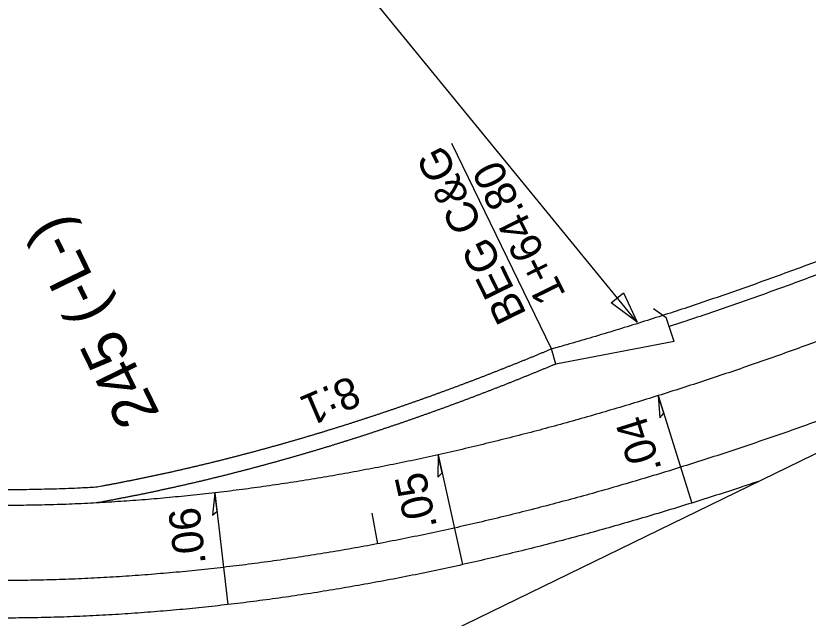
# Model space of a CAD drawing. Extents: x 2389694 to 2405615, y 546931 to 573532.
# Drawn here: x 2402110.3 to 2402237.1, y 570891.7 to 570988.1 of the extents above; entities that cross this region are included whole.
import ezdxf

# ---------------------------------------------------------------- set-up
doc = ezdxf.new("R2010")
doc.units = 0
for name, color, linetype in [('Old_Level_5', 7, 'Continuous'), ('Prop Cable Guiderail Single Face', 7, 'Continuous'), ('Prop Conc 2ft 6in Curb and Gutter', 7, 'Continuous'), ('Prop Conc Expressway Gutter', 7, 'Continuous'), ('Prop Dimension', 7, 'Continuous'), ('Prop Dimension Text', 7, 'Continuous'), ('Prop EOT', 7, 'Continuous'), ('Prop Horizontal Alignment', 7, 'Continuous'), ('Prop Horizontal Alignment Curve and Spiral Data', 7, 'Continuous'), ('Prop Horizontal Alignment Tick Small', 7, 'Continuous'), ('Prop Lane Lines', 7, 'Continuous'), ('Prop Super Arrow 1 Lane CELL', 7, 'Continuous'), ('Prop Superelevation Label', 7, 'Continuous')]:
    doc.layers.add(name, color=color, linetype=linetype)

msp = doc.modelspace()

# ---------------------------------------------------------------- linework, layer by layer
at = {"layer": 'Old_Level_5'}
msp.add_line((2402209.7, 570939.08), (2402131.29, 571034.89), dxfattribs=at)
msp.add_lwpolyline([(2402207.5, 570943.74), (2402209.7, 570939.08), (2402205.56, 570942.16)], close=True, dxfattribs=at)
at = {"layer": 'Prop Cable Guiderail Single Face'}
msp.add_spline([(2402278.77, 570901.45), (2402277.96, 570901.06), (2402277.14, 570900.67), (2402276.32, 570900.29), (2402275.51, 570899.9), (2402274.7, 570899.51), (2402273.88, 570899.13), (2402273.07, 570898.74), (2402272.26, 570898.36), (2402271.44, 570897.97), (2402270.63, 570897.58), (2402269.82, 570897.2), (2402269.01, 570896.81), (2402268.18, 570896.42), (2402267.37, 570896.04), (2402266.56, 570895.65), (2402265.74, 570895.26), (2402264.93, 570894.88), (2402264.12, 570894.49), (2402263.31, 570894.11), (2402262.49, 570893.72), (2402261.68, 570893.33), (2402260.87, 570892.95), (2402260.05, 570892.56), (2402259.24, 570892.18), (2402258.42, 570891.79), (2402257.6, 570891.4), (2402256.79, 570891.01), (2402255.98, 570890.63), (2402255.17, 570890.24), (2402254.35, 570889.86), (2402253.54, 570889.47), (2402252.73, 570889.08), (2402251.91, 570888.7), (2402251.1, 570888.31), (2402250.29, 570887.93), (2402249.47, 570887.53), (2402248.65, 570887.15), (2402247.84, 570886.76), (2402247.03, 570886.38), (2402246.21, 570885.99), (2402245.4, 570885.6), (2402244.59, 570885.22), (2402243.77, 570884.83), (2402242.96, 570884.45), (2402242.15, 570884.06), (2402241.33, 570883.67), (2402240.51, 570883.28), (2402239.7, 570882.9), (2402238.89, 570882.51), (2402238.07, 570882.13), (2402237.26, 570881.74), (2402236.45, 570881.35), (2402235.63, 570880.97), (2402234.82, 570880.58), (2402234.01, 570880.2), (2402233.19, 570879.81), (2402232.38, 570879.42), (2402231.56, 570879.03), (2402230.75, 570878.65), (2402229.93, 570878.26), (2402229.12, 570877.88), (2402228.31, 570877.49), (2402227.49, 570877.1), (2402226.68, 570876.72), (2402225.87, 570876.33), (2402225.06, 570875.95), (2402224.24, 570875.56), (2402223.43, 570875.17), (2402222.61, 570874.78), (2402221.79, 570874.4), (2402220.98, 570874.01), (2402220.17, 570873.62), (2402218.54, 570872.85)], degree=3, dxfattribs=at)
at = {"layer": 'Prop Conc 2ft 6in Curb and Gutter'}
msp.add_line((2402212.33, 570941.22), (2402214.37, 570939.78), dxfattribs=at)
for points in [[(2402196.02, 570934.77), (2402195.54, 570934.57), (2402195.07, 570934.37), (2402194.59, 570934.18), (2402194.11, 570933.98), (2402193.64, 570933.78), (2402193.16, 570933.58), (2402192.68, 570933.39), (2402192.2, 570933.19), (2402191.73, 570933), (2402191.25, 570932.81), (2402190.77, 570932.61), (2402190.29, 570932.42), (2402189.81, 570932.23), (2402189.33, 570932.04), (2402188.85, 570931.85), (2402188.38, 570931.66), (2402187.9, 570931.47), (2402187.42, 570931.28), (2402186.94, 570931.09), (2402186.46, 570930.9), (2402185.97, 570930.71), (2402185.49, 570930.53), (2402185.01, 570930.34), (2402184.53, 570930.15), (2402184.05, 570929.97), (2402183.57, 570929.79), (2402183.09, 570929.6), (2402182.6, 570929.42), (2402182.12, 570929.24), (2402181.64, 570929.06), (2402181.16, 570928.87), (2402180.67, 570928.69), (2402180.19, 570928.51), (2402179.71, 570928.34), (2402179.22, 570928.16), (2402178.74, 570927.98), (2402178.25, 570927.8), (2402177.77, 570927.63), (2402177.28, 570927.45), (2402176.8, 570927.27), (2402176.31, 570927.1), (2402175.83, 570926.93), (2402175.34, 570926.75), (2402174.86, 570926.58), (2402174.37, 570926.41), (2402173.88, 570926.24), (2402173.4, 570926.07), (2402172.91, 570925.9), (2402172.42, 570925.73), (2402171.94, 570925.56), (2402171.45, 570925.39), (2402170.96, 570925.22), (2402170.47, 570925.06), (2402169.98, 570924.89), (2402169.49, 570924.72), (2402169.01, 570924.56), (2402168.52, 570924.4), (2402168.03, 570924.23), (2402167.54, 570924.07), (2402167.05, 570923.91), (2402166.56, 570923.75), (2402166.07, 570923.59), (2402165.58, 570923.43), (2402165.09, 570923.27), (2402164.59, 570923.11), (2402164.1, 570922.95), (2402163.61, 570922.79), (2402163.12, 570922.64), (2402162.63, 570922.48), (2402162.14, 570922.33), (2402161.64, 570922.17), (2402161.15, 570922.02), (2402160.66, 570921.87), (2402160.16, 570921.72)], [(2402160.16, 570921.72), (2402159.67, 570921.56), (2402159.18, 570921.41), (2402158.68, 570921.26), (2402158.19, 570921.12), (2402157.69, 570920.97), (2402157.2, 570920.82), (2402156.7, 570920.67), (2402156.21, 570920.53), (2402155.71, 570920.38), (2402155.22, 570920.24), (2402154.72, 570920.09), (2402154.23, 570919.95), (2402153.73, 570919.81), (2402153.23, 570919.67), (2402152.74, 570919.53), (2402152.24, 570919.39), (2402151.74, 570919.25), (2402151.24, 570919.11), (2402150.75, 570918.97), (2402150.25, 570918.83), (2402149.75, 570918.7), (2402149.25, 570918.56), (2402148.75, 570918.43), (2402148.25, 570918.29), (2402147.75, 570918.16), (2402147.25, 570918.03), (2402146.75, 570917.9), (2402146.25, 570917.76), (2402145.75, 570917.63), (2402145.25, 570917.51), (2402144.75, 570917.38), (2402144.25, 570917.25), (2402143.75, 570917.12), (2402143.25, 570917), (2402142.75, 570916.87), (2402142.25, 570916.75), (2402141.74, 570916.62), (2402141.24, 570916.5), (2402140.74, 570916.38), (2402140.23, 570916.26), (2402139.73, 570916.14), (2402139.23, 570916.02), (2402138.72, 570915.9), (2402138.22, 570915.78), (2402137.72, 570915.66), (2402137.21, 570915.55), (2402136.71, 570915.43), (2402136.2, 570915.32), (2402135.7, 570915.2), (2402135.19, 570915.09), (2402134.69, 570914.98), (2402134.18, 570914.87), (2402133.68, 570914.76), (2402133.17, 570914.65), (2402132.66, 570914.54), (2402132.16, 570914.43), (2402131.65, 570914.32), (2402131.14, 570914.22), (2402130.64, 570914.11), (2402130.13, 570914.01), (2402129.62, 570913.9), (2402129.11, 570913.8), (2402128.6, 570913.7), (2402128.1, 570913.6), (2402127.59, 570913.5), (2402127.08, 570913.4), (2402126.57, 570913.3), (2402126.06, 570913.2), (2402125.55, 570913.11), (2402125.04, 570913.01), (2402124.53, 570912.92), (2402124.02, 570912.82), (2402123, 570912.64)], [(2402123, 570912.64), (2402120.62, 570912.52), (2402116.77, 570912.37), (2402112.91, 570912.28), (2402109.06, 570912.23), (2402105.21, 570912.24), (2402101.37, 570912.31), (2402097.53, 570912.43), (2402093.69, 570912.61), (2402089.86, 570912.84), (2402086.04, 570913.14), (2402082.23, 570913.49), (2402078.42, 570913.9), (2402074.63, 570914.36), (2402070.73, 570914.91)]]:
    msp.add_spline(points, degree=3, dxfattribs=at)
at = {"layer": 'Prop Conc Expressway Gutter'}
msp.add_spline([(2402344.87, 570994.4), (2402341.23, 570992.63), (2402337.59, 570990.86), (2402333.96, 570989.09), (2402330.32, 570987.33), (2402326.7, 570985.57), (2402323.07, 570983.82), (2402319.44, 570982.08), (2402315.82, 570980.34), (2402312.2, 570978.61), (2402308.58, 570976.9), (2402304.96, 570975.19), (2402301.33, 570973.49), (2402297.71, 570971.8), (2402294.09, 570970.13), (2402290.47, 570968.47), (2402286.85, 570966.82), (2402283.23, 570965.19), (2402279.6, 570963.57), (2402275.97, 570961.97), (2402272.34, 570960.39), (2402268.71, 570958.82), (2402265.08, 570957.28), (2402261.44, 570955.75), (2402257.8, 570954.24), (2402254.15, 570952.76), (2402250.5, 570951.29), (2402246.85, 570949.85), (2402243.2, 570948.43), (2402239.54, 570947.04), (2402235.87, 570945.67), (2402232.2, 570944.33), (2402228.53, 570943.01), (2402224.85, 570941.72), (2402221.17, 570940.46), (2402217.48, 570939.22), (2402214.83, 570938.36)], degree=3, dxfattribs=at)
at = {"layer": 'Prop Dimension'}
msp.add_line((2402196.02, 570934.77), (2402180.02, 570967.65), dxfattribs=at)
at = {"layer": 'Prop EOT'}
for p, q in [((2402215.66, 570935.99), (2402214.37, 570939.78)), ((2402215.66, 570935.99), (2402196.69, 570932.36)), ((2402196.69, 570932.36), (2402196.02, 570934.77))]:
    msp.add_line(p, q, dxfattribs=at)
for points in [[(2402344, 570996.2), (2402340.36, 570994.43), (2402336.72, 570992.66), (2402333.08, 570990.89), (2402329.45, 570989.13), (2402325.82, 570987.37), (2402322.2, 570985.62), (2402318.58, 570983.88), (2402314.96, 570982.15), (2402311.34, 570980.42), (2402307.72, 570978.7), (2402304.1, 570977), (2402300.49, 570975.3), (2402296.87, 570973.62), (2402293.26, 570971.95), (2402289.64, 570970.29), (2402286.02, 570968.64), (2402282.41, 570967.02), (2402278.79, 570965.4), (2402275.17, 570963.8), (2402271.55, 570962.23), (2402267.92, 570960.66), (2402264.3, 570959.12), (2402260.67, 570957.6), (2402257.04, 570956.09), (2402253.4, 570954.61), (2402249.76, 570953.15), (2402246.12, 570951.71), (2402242.48, 570950.3), (2402238.83, 570948.91), (2402235.18, 570947.54), (2402231.52, 570946.21), (2402227.86, 570944.89), (2402224.2, 570943.61), (2402220.53, 570942.35), (2402216.86, 570941.12), (2402213.18, 570939.93), (2402209.5, 570938.76), (2402205.81, 570937.62), (2402202.12, 570936.52), (2402198.43, 570935.45), (2402196.02, 570934.77)], [(2402349.25, 570985.41), (2402345.61, 570983.64), (2402341.96, 570981.86), (2402338.32, 570980.1), (2402334.68, 570978.33), (2402331.05, 570976.57), (2402327.41, 570974.81), (2402323.77, 570973.06), (2402320.13, 570971.32), (2402316.49, 570969.58), (2402312.85, 570967.86), (2402309.21, 570966.14), (2402305.57, 570964.43), (2402301.92, 570962.73), (2402298.28, 570961.05), (2402294.63, 570959.37), (2402290.97, 570957.71), (2402287.32, 570956.06), (2402283.65, 570954.43), (2402279.99, 570952.82), (2402276.32, 570951.22), (2402272.65, 570949.63), (2402268.97, 570948.07), (2402265.29, 570946.52), (2402261.6, 570944.99), (2402257.9, 570943.49), (2402254.2, 570942), (2402250.5, 570940.54), (2402246.78, 570939.1), (2402243.07, 570937.68), (2402239.34, 570936.29), (2402235.61, 570934.92), (2402231.87, 570933.58), (2402228.13, 570932.27), (2402224.37, 570930.98), (2402220.62, 570929.73), (2402216.85, 570928.5), (2402213.08, 570927.31), (2402209.3, 570926.14), (2402205.51, 570925.01), (2402201.72, 570923.91), (2402197.91, 570922.84), (2402194.11, 570921.81), (2402190.29, 570920.82), (2402186.47, 570919.86), (2402182.64, 570918.94), (2402178.81, 570918.06), (2402174.97, 570917.21), (2402171.12, 570916.41), (2402167.27, 570915.65), (2402163.41, 570914.93), (2402159.55, 570914.25), (2402155.68, 570913.62), (2402151.81, 570913.03), (2402147.94, 570912.49), (2402144.06, 570911.99), (2402140.18, 570911.54), (2402136.29, 570911.14), (2402132.4, 570910.78), (2402128.52, 570910.48), (2402124.63, 570910.23), (2402120.74, 570910.02), (2402116.85, 570909.87), (2402112.96, 570909.78), (2402109.07, 570909.73), (2402105.19, 570909.74), (2402101.31, 570909.81), (2402097.43, 570909.93), (2402093.56, 570910.11), (2402089.69, 570910.35), (2402085.83, 570910.64), (2402081.98, 570911), (2402078.13, 570911.41), (2402074.3, 570911.89), (2402070.38, 570912.43)], [(2402196.69, 570932.36), (2402196.21, 570932.16), (2402195.73, 570931.96), (2402195.25, 570931.76), (2402194.77, 570931.57), (2402194.29, 570931.37), (2402193.81, 570931.17), (2402193.33, 570930.98), (2402192.85, 570930.78), (2402192.37, 570930.58), (2402191.89, 570930.39), (2402191.41, 570930.2), (2402190.93, 570930), (2402190.45, 570929.81), (2402189.96, 570929.62), (2402189.48, 570929.43), (2402189, 570929.23), (2402188.52, 570929.04), (2402188.03, 570928.85), (2402187.55, 570928.67), (2402187.07, 570928.48), (2402186.58, 570928.29), (2402186.1, 570928.1), (2402185.62, 570927.91), (2402185.13, 570927.73), (2402184.65, 570927.54), (2402184.16, 570927.36), (2402183.68, 570927.17), (2402183.19, 570926.99), (2402182.71, 570926.81), (2402182.22, 570926.62), (2402181.73, 570926.44), (2402181.25, 570926.26), (2402180.76, 570926.08), (2402180.27, 570925.9), (2402179.79, 570925.72), (2402179.3, 570925.54), (2402178.81, 570925.36), (2402178.32, 570925.19), (2402177.84, 570925.01), (2402177.35, 570924.83), (2402176.86, 570924.66), (2402176.37, 570924.48), (2402175.88, 570924.31), (2402175.39, 570924.14), (2402174.9, 570923.96), (2402174.41, 570923.79), (2402173.92, 570923.62), (2402173.43, 570923.45), (2402172.94, 570923.28), (2402172.45, 570923.11), (2402171.96, 570922.94), (2402171.47, 570922.77), (2402170.98, 570922.61), (2402170.48, 570922.44), (2402169.99, 570922.27), (2402169.5, 570922.11), (2402169.01, 570921.94), (2402168.51, 570921.78), (2402168.02, 570921.62), (2402167.53, 570921.45), (2402167.03, 570921.29), (2402166.54, 570921.13), (2402166.05, 570920.97), (2402165.55, 570920.81), (2402165.06, 570920.65), (2402164.56, 570920.49), (2402164.07, 570920.34), (2402163.57, 570920.18), (2402163.08, 570920.02), (2402162.58, 570919.87), (2402162.08, 570919.71), (2402161.59, 570919.56), (2402161.09, 570919.41), (2402160.6, 570919.25)], [(2402160.6, 570919.25), (2402160.1, 570919.1), (2402159.6, 570918.95), (2402159.1, 570918.8), (2402158.61, 570918.65), (2402158.11, 570918.5), (2402157.61, 570918.35), (2402157.11, 570918.21), (2402156.61, 570918.06), (2402156.11, 570917.91), (2402155.61, 570917.77), (2402155.11, 570917.62), (2402154.61, 570917.48), (2402154.11, 570917.34), (2402153.61, 570917.19), (2402153.11, 570917.05), (2402152.61, 570916.91), (2402152.11, 570916.77), (2402151.61, 570916.63), (2402151.11, 570916.5), (2402150.6, 570916.36), (2402150.1, 570916.22), (2402149.6, 570916.09), (2402149.1, 570915.95), (2402148.59, 570915.82), (2402148.09, 570915.68), (2402147.59, 570915.55), (2402147.08, 570915.42), (2402146.58, 570915.29), (2402146.08, 570915.16), (2402145.57, 570915.03), (2402145.07, 570914.9), (2402144.56, 570914.77), (2402144.06, 570914.64), (2402143.55, 570914.51), (2402143.04, 570914.39), (2402142.54, 570914.26), (2402142.03, 570914.14), (2402141.53, 570914.02), (2402141.02, 570913.89), (2402140.51, 570913.77), (2402140.01, 570913.65), (2402139.5, 570913.53), (2402138.99, 570913.41), (2402138.48, 570913.29), (2402137.97, 570913.18), (2402137.47, 570913.06), (2402136.96, 570912.94), (2402136.45, 570912.83), (2402135.94, 570912.72), (2402135.43, 570912.6), (2402134.92, 570912.49), (2402134.41, 570912.38), (2402133.9, 570912.27), (2402133.39, 570912.16), (2402132.88, 570912.05), (2402132.37, 570911.94), (2402131.86, 570911.83), (2402131.35, 570911.73), (2402130.83, 570911.62), (2402130.32, 570911.52), (2402129.81, 570911.41), (2402129.3, 570911.31), (2402128.79, 570911.21), (2402128.27, 570911.11), (2402127.76, 570911.01), (2402127.25, 570910.91), (2402126.73, 570910.81), (2402126.22, 570910.71), (2402125.71, 570910.61), (2402125.19, 570910.52), (2402124.68, 570910.42), (2402124.16, 570910.33), (2402123.13, 570910.14)], [(2402277.06, 570905.06), (2402276.24, 570904.68), (2402275.42, 570904.29), (2402274.61, 570903.9), (2402273.79, 570903.51), (2402272.98, 570903.13), (2402272.17, 570902.74), (2402271.36, 570902.36), (2402270.54, 570901.97), (2402269.73, 570901.58), (2402268.92, 570901.2), (2402268.1, 570900.81), (2402267.29, 570900.43), (2402266.47, 570900.04), (2402265.65, 570899.65), (2402264.84, 570899.26), (2402264.03, 570898.88), (2402263.22, 570898.49), (2402262.4, 570898.11), (2402261.59, 570897.72), (2402260.78, 570897.33), (2402259.96, 570896.95), (2402259.15, 570896.56), (2402258.34, 570896.18), (2402257.52, 570895.79), (2402256.7, 570895.4), (2402255.89, 570895.01), (2402255.08, 570894.63), (2402254.26, 570894.24), (2402253.45, 570893.85), (2402252.64, 570893.47), (2402251.82, 570893.08), (2402251.01, 570892.7), (2402250.2, 570892.31), (2402249.38, 570891.92), (2402248.57, 570891.54), (2402247.75, 570891.15), (2402246.94, 570890.76), (2402246.12, 570890.38), (2402245.31, 570889.99), (2402244.5, 570889.6), (2402243.68, 570889.22), (2402242.87, 570888.83), (2402242.06, 570888.45), (2402241.24, 570888.06), (2402240.43, 570887.67), (2402239.62, 570887.29), (2402238.8, 570886.9), (2402237.98, 570886.51), (2402237.17, 570886.13), (2402236.36, 570885.74), (2402235.54, 570885.35), (2402234.73, 570884.97), (2402233.92, 570884.58), (2402233.11, 570884.2), (2402232.29, 570883.81), (2402231.48, 570883.42), (2402230.67, 570883.04), (2402229.84, 570882.65), (2402229.03, 570882.26), (2402228.22, 570881.87), (2402227.41, 570881.49), (2402226.59, 570881.1), (2402225.78, 570880.72), (2402224.97, 570880.33), (2402224.15, 570879.94), (2402223.34, 570879.56), (2402222.53, 570879.17), (2402221.71, 570878.79), (2402220.89, 570878.4), (2402220.08, 570878.01), (2402219.27, 570877.62), (2402218.45, 570877.24), (2402216.83, 570876.47)]]:
    msp.add_spline(points, degree=3, dxfattribs=at)
at = {"layer": 'Prop Horizontal Alignment'}
msp.add_arc((2399929.8, 569697.99), 2887.13, 22.84477, 37.67936, dxfattribs=at)
msp.add_spline([(2402354.5, 570974.62), (2402350.86, 570972.84), (2402347.21, 570971.07), (2402343.56, 570969.3), (2402339.92, 570967.53), (2402336.27, 570965.76), (2402332.62, 570964), (2402328.96, 570962.24), (2402325.31, 570960.49), (2402321.65, 570958.75), (2402317.99, 570957.01), (2402314.32, 570955.28), (2402310.65, 570953.56), (2402306.97, 570951.85), (2402303.29, 570950.15), (2402299.61, 570948.46), (2402295.92, 570946.78), (2402292.22, 570945.11), (2402288.52, 570943.46), (2402284.81, 570941.83), (2402281.09, 570940.21), (2402277.37, 570938.6), (2402273.64, 570937.01), (2402269.9, 570935.44), (2402266.16, 570933.89), (2402262.4, 570932.36), (2402258.64, 570930.85), (2402254.87, 570929.36), (2402251.09, 570927.9), (2402247.3, 570926.45), (2402243.5, 570925.04), (2402239.7, 570923.64), (2402235.88, 570922.27), (2402232.06, 570920.93), (2402228.22, 570919.62), (2402224.38, 570918.33), (2402220.52, 570917.08), (2402216.66, 570915.85), (2402212.78, 570914.66), (2402208.9, 570913.5), (2402205, 570912.37), (2402201.1, 570911.27), (2402197.19, 570910.22), (2402193.26, 570909.19), (2402189.33, 570908.21), (2402185.39, 570907.26), (2402181.44, 570906.35), (2402177.48, 570905.48), (2402173.51, 570904.65), (2402169.53, 570903.87), (2402165.55, 570903.12), (2402161.56, 570902.42), (2402157.56, 570901.77), (2402153.55, 570901.16), (2402149.53, 570900.59), (2402145.51, 570900.08), (2402141.48, 570899.61), (2402137.45, 570899.19), (2402133.41, 570898.83), (2402129.37, 570898.51), (2402125.33, 570898.25), (2402121.28, 570898.04), (2402117.23, 570897.88), (2402113.18, 570897.78), (2402109.12, 570897.73), (2402105.07, 570897.75), (2402101.01, 570897.81), (2402096.96, 570897.94), (2402092.91, 570898.13), (2402088.87, 570898.38), (2402084.82, 570898.69), (2402080.79, 570899.06), (2402076.76, 570899.49), (2402072.73, 570899.99), (2402068.72, 570900.55)], degree=3, dxfattribs=at)
at = {"layer": 'Prop Horizontal Alignment Tick Small'}
msp.add_line((2402168.21, 570903.61), (2402167.28, 570908.53), dxfattribs=at)
at = {"layer": 'Prop Lane Lines'}
msp.add_line((2402011.52, 570807.67), (2402377.08, 570985.61), dxfattribs=at)
msp.add_spline([(2402229.11, 570913.59), (2402226.26, 570912.63), (2402222.36, 570911.36), (2402218.45, 570910.13), (2402214.53, 570908.92), (2402210.59, 570907.74), (2402206.65, 570906.6), (2402202.69, 570905.49), (2402198.73, 570904.42), (2402194.75, 570903.38), (2402190.76, 570902.38), (2402186.76, 570901.42), (2402182.76, 570900.5), (2402178.74, 570899.61), (2402174.71, 570898.77), (2402170.67, 570897.97), (2402166.62, 570897.22), (2402162.56, 570896.51), (2402158.49, 570895.84), (2402154.42, 570895.22), (2402150.33, 570894.65), (2402146.24, 570894.12), (2402142.14, 570893.65), (2402138.03, 570893.22), (2402133.92, 570892.85), (2402129.8, 570892.53), (2402125.68, 570892.26), (2402121.55, 570892.04), (2402117.42, 570891.88), (2402113.28, 570891.78), (2402109.15, 570891.73), (2402105.01, 570891.75), (2402100.87, 570891.82), (2402096.73, 570891.95), (2402092.59, 570892.14), (2402088.45, 570892.39), (2402084.32, 570892.71), (2402080.19, 570893.09), (2402076.07, 570893.53), (2402071.95, 570894.04), (2402067.89, 570894.61)], degree=3, dxfattribs=at)
at = {"layer": 'Prop Super Arrow 1 Lane CELL'}
for p, q in [((2402213.08, 570927.31), (2402218.45, 570910.13)), ((2402177.85, 570917.84), (2402181.75, 570900.27)), ((2402142.12, 570911.76), (2402144.19, 570893.88))]:
    msp.add_line(p, q, dxfattribs=at)
for points in [[(2402213.08, 570927.31), (2402213.36, 570923.73), (2402213.96, 570924.49)], [(2402177.85, 570917.84), (2402177.83, 570914.25), (2402178.49, 570914.96)], [(2402142.12, 570911.76), (2402141.72, 570908.19), (2402142.46, 570908.83)]]:
    msp.add_lwpolyline(points, close=True, dxfattribs=at)

# ---------------------------------------------------------------- texts
at = {"layer": 'Prop Dimension Text'}
for s, rotation, p in [('BEG C&G', 116.1339, (2402192.08, 570940.37)), ('1+64.80', 116.1339, (2402198.36, 570943.45)), ('8:1', 203.1454, (2402163.97, 570930.59))]:
    msp.add_text(s, height=5, rotation=rotation, dxfattribs=at).set_placement(p)
at = {"layer": 'Prop Horizontal Alignment Curve and Spiral Data'}
msp.add_text('245 (-L-)', height=7, rotation=115.9541, dxfattribs=at).set_placement((2402133.37, 570924.37))
at = {"layer": 'Prop Superelevation Label'}
for s, rotation, p in [('.04', 107.3597, (2402213.7, 570915.57)), ('.05', 102.5254, (2402177.72, 570906.34)), ('.06', 96.6168, (2402140.68, 570900.44))]:
    msp.add_text(s, height=5, rotation=rotation, dxfattribs=at).set_placement(p)

doc.saveas('drawing.dxf')
